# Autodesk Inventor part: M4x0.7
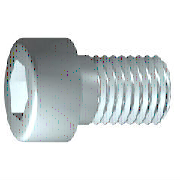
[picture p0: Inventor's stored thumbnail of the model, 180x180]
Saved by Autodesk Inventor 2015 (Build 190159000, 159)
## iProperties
IsCustomPart: 1
Created: 2015-10
Part Number: M4x0.7
Material: Steel, Mild
Description: 6각머리 태핑 나사
Document SubType Name: Modeling
Standard: KS B 1003
Designer: mdu
Standards Organization: KS
Language: ko-KR
Size Designation: M 4 x 16
Categories: <MemberInstance><Categories><Category DisplayName="조임쇠" InternalName="e4da775c-781d-43d5-af7c-5136215cf5a6" Mnemonic="FSTN"><Category DisplayName="볼트" InternalN
Density: 1 g/cm^3
Appearance: Steel
Author: mdu
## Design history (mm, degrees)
revolve "본체" stored, may be unused: angle "d10" = 90 deg
sketch "스케치2"
  geometry: L1 (0, -4.9)-(0, 4.9) reference; L2 (-4.9, 0)-(4.9, 0) reference; L3 (1.732, 0)-(0.866, -1.5); L4 (0.866, -1.5)-(-0.866, -1.5); L5 (-0.866, -1.5)-(-1.732, 0); L6 (-1.732, 0)-(-0.866, 1.5); L7 (-0.866, 1.5)-(0.866, 1.5); L8 (0.866, 1.5)-(1.732, 0); 2 further points
  constraints: 12 end point, 1 coincident, 1 horizontal alignment, 1 point on line, 12 other
extrude "슬롯" join sketch "스케치2" stored distance "d11" = 10; taper "d12" = 0 deg
workplane "Work Plane1"
fillet "Fillet2" dims "d30" = 0.1 (= R)
body "Solid1"
fillet "모깎기1" dims "d17" = 0.4 (= RR)
feature "스레드" dims "d13" = 14.25 (= GEL), "d14" = 0
chamfer "모따기1" distance "d15" = 0.42941 (= -0.5 x SPD + 0.5 x GD); stored, may be unused: second distance "d16" = 0.42941 (= GUL), angle "d27" = 45 deg
sketch "스케치1"
  geometry: L1 (-1, 0)-(16, 0); L2 (16, 0)-(16, 2); L3 (16, 2)-(1.75, 2); L4 (1.75, 2)-(1.32, 2); L5 (1.32, 2)-(0, 2); L6 (0, 2)-(0, 3.5); L7 (0, 3.5)-(-4, 3.5); L8 (-4, 3.5)-(-4, 1.732); L9 (-4, 1.732)-(-2, 1.732); L10 (-2, 1.732)-(-1, 0); L11 (-8, 0)-(20, 0) reference; L12 (0, -0.7)-(0, 4.2) reference; L13 (1.75, 2)-(0, 2)
  constraints: 22 end point, 6 parallel, 2 collinear, 2 perpendicular, 1 horizontal, 1 point on line
  dimensions: "d1" = 14.25 distance from line of L3.end L2 (= GEL); "d2" = 0.42952 distance of L4.end L3.end (computed from GAL); "d3" = 4 distance between parallel lines of L8 L6 (= KOH); "d4" = 2 distance of L8.end L9.end (= INTI); "d5" = 60 deg angle of L10 L1; "d6" = 4 diameter of L3 L1 (= GD); "d7" = 4 diameter of L5 L1 (= BDM); "d8" = 3.4641 diameter of L9 L1 (= 1.1547 x SW); "d9" = 7 diameter of L7 L1 (= KOD); "d26" = 16 distance between parallel lines of L12 L2 (= NLG)
other parameters: "GD" = 4 (= NND) [user parameter; used in 2 equation terms], "NLG" = 16 [user parameter; used in 1 equation term], "GEL" = 14.25 [user parameter; used in 2 equation terms], "KOD" = 7 [user parameter; used in 1 equation term], "KOH" = 4 [user parameter; used in 1 equation term], "INTI" = 2 [user parameter; used in 1 equation term], "GAL" = 0.42941 (= 0.61345 x PTC) [user parameter; used in 1 equation term], "GUL" = 0.42941 (= 0.61345 x PTC) [user parameter; used in 1 equation term], "BDM" = 4 (= NND) [user parameter; used in 1 equation term], "SW" = 3 [user parameter; used in 2 equation terms], "RR" = 0.4 [user parameter; used in 1 equation term], "SPD" = 3.14117 (= NND - 1.2269 x PTC) [user parameter; used in 1 equation term], "d19" = 0, "d28" = 0, "d29" = 0, "R" = 0.1 [user parameter; used in 1 equation term], "PHH" = 0.2 [user parameter], "GD1" = 3.14117 (= THREADDIA - 1.2269 x PTC) [user parameter], "THREADDIA" = 4 [user parameter; used in 1 equation term], "FAWI" = 45 deg [user parameter], "TPU" = 14.28571 (computed from PTC) [user parameter], "PTC" = 0.7 [user parameter; used in 5 equation terms], "NND" = 4 [user parameter; used in 3 equation terms], "TOA" = 30 deg [user parameter], "E0" = 3.465 (= 1.155 x SW) [user parameter]
